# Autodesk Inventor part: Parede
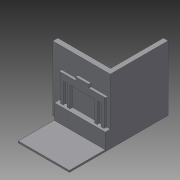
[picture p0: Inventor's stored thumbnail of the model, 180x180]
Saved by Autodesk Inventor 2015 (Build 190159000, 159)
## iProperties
Created: 2015-04
Part Number: Parede
Material: Genérico
Document SubType Name: Modeling
Designer: Felipe
Density: 1 g/cm^3
Appearance: Padrão
Author: Felipe
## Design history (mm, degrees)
sketch "Sketch1"
  geometry: L1 (0, 0)-(16900, 0); L2 (16900, 0)-(16900, 17000); L3 (16900, 17000)-(15500, 17000); L4 (15500, 17000)-(15500, 1500); L5 (15500, 1500)-(0, 1500); L6 (0, 1500)-(0, 0)
  constraints: 12 end point, 5 perpendicular, 1 horizontal
  dimensions: "d0" = 1500 distance between parallel lines of L5 L1; "d1" = 1400 distance between parallel lines of L2 L4; "d2" = 16900 distance between parallel lines of L2 L6; "d3" = 17000 distance between parallel lines of L3 L1
extrude "Extrusion1" new body sketch "Sketch1" distance "d4" = 19000; taper "d5" = 0 deg
sketch "Sketch2"
  geometry: L1 (16900, 0)-(1880, 0); L2 (1880, 0)-(1880, 500); L3 (1880, 500)-(16900, 500); L4 (16900, 500)-(16900, 0); L5 (0, 0)-(16900, 0) reference; L6 (16900, 0)-(16900, 19000) reference; L7 (0, 19000)-(16900, 19000) reference; L8 (0, 0)-(0, 19000) reference; L9 (16900, 0)-(16900, 19000) reference; L10 (0, 0)-(16900, 0) reference
  constraints: 8 end point, 2 collinear, 2 parallel, 1 horizontal, 1 perpendicular
  dimensions: "d6" = 15020 distance between parallel lines of L4 L2; "d7" = 500 distance between parallel lines of L3 L1
extrude "Extrusion2" join sketch "Sketch2" distance "d8" = 12010; taper "d9" = 0 deg
sketch "Sketch3"
  geometry: L1 (1880, -18500)-(16900, -18500) reference; L2 (16900, -18500)-(16900, 0) reference; L3 (0, 0)-(16900, 0) reference; L4 (0, -19000)-(0, 0) reference; L5 (0, -19000)-(1880, -19000) reference; L6 (1880, -19000)-(1880, -18500) reference; L7 (1880, -19000)-(16900, -19000) reference; L8 (16900, -19000)-(16900, -18500) reference; L9 (16900, -18500)-(1880, -18500) reference; L10 (1880, -18500)-(1880, -19000) reference; L11 (16900, -14000)-(1980, -14000); L12 (1980, -14000)-(1980, -19000); L13 (16900, -18500)-(1880, -18500); L14 (16900, -14000)-(16900, -18500); L15 (1980, -14000)-(16900, -14000); L16 (16900, -14000)-(16900, -18500); L17 (16900, -18500)-(1980, -18500); L18 (1980, -18500)-(1980, -14000); 1 further point
  constraints: 16 end point, 3 equal length, 3 perpendicular, 2 point on line, 1 horizontal, 1 vertical
  dimensions: "d11" = 4500 distance between parallel lines of L11 L1
extrude "Extrusion4" join sketch "Sketch3" distance "d14" = 1480; taper "d15" = 0 deg
sketch "Sketch4"
  geometry: L1 (1980, -18500)-(1980, -14000) reference; L2 (1980, -14000)-(16900, -14000) reference; L3 (16900, -14000)-(16900, 0) reference; L4 (0, 0)-(16900, 0) reference; L5 (0, -19000)-(0, 0) reference; L6 (0, -19000)-(1880, -19000) reference; L7 (1880, -19000)-(1880, -18500) reference; L8 (1880, -18500)-(1980, -18500) reference; L9 (1980, -14000)-(1980, -18500) reference; L10 (16900, -18500)-(1980, -18500) reference; L11 (16900, -18500)-(16900, -14000) reference; L12 (16900, -18500)-(1880, -18500) reference; L13 (1980, -14000)-(1980, -18500) reference; L14 (2980, -14000)-(2980, -7920); L15 (2980, -7920)-(3800, -7920); L16 (3800, -7920)-(3800, -14000); L17 (4980, -14000)-(4980, -7920); L18 (4980, -7920)-(5800, -7920); L19 (5800, -7920)-(5800, -14000); L20 (12980, -14000)-(12980, -7920); L21 (12980, -7920)-(13800, -7920); L22 (13800, -7920)-(13706.466, -7920); L23 (13800, -7920)-(13800, -14000); L24 (14980, -14000)-(14980, -7920); L25 (14980, -7920)-(15800, -7920); L26 (15500, -19000)-(15500, 0) reference; L27 (15800, -7920)-(15800, -14000); L28 (2980, -7920)-(15800, -7920); L29 (15800, -7920)-(15800, -6420); L30 (15800, -6420)-(2980, -6420); L31 (2980, -6420)-(2980, -7920); L32 (2574, -6000)-(16206, -6000); L33 (2980, -6420)-(2574, -6000); L34 (15800, -6420)-(16206, -6000); L35 (7480, -5000)-(11300, -5000); L36 (7480, -5000)-(7480, -6000); L37 (11300, -5000)-(11300, -6000); 4 further points
  constraints: 46 end point, 8 perpendicular, 5 vertical, 3 horizontal, 3 midpoint, 3 parallel, 3 point on line, 2 vertical alignment, 1 collinear, 9 other
  dimensions: "d16" = 1000 distance between parallel lines of L14 L9; "d17" = 820 distance between parallel lines of L16 L14; "d18" = 6080 distance between parallel lines of L2 L15; "d19" = 820 distance of L17.end L18.end; "d20" = 1180 distance between parallel lines of L17 L16; "d21" = 6080 distance between parallel lines of L2 L18; "d22" = 820 distance of L20.end L21.end; "d23" = 7180 distance between parallel lines of L20 L19; "d24" = 6080 distance between parallel lines of L2 L21; "d25" = 820 distance of L24.end L25.end; "d26" = 1180 distance between parallel lines of L24 L23; "d27" = 1500 distance between parallel lines of L30 L28; "d28" = 12820 distance between parallel lines of L29 L31; "d29" = 13632 distance of L32.start L32.end; "d30" = 420 distance between parallel lines of L32 L30; "d31" = 3820 distance of L35.start L35.end; "d32" = 1000 distance between parallel lines of L32 L35
extrude "Extrusion5" join sketch "Sketch4" distance "d33" = 740; taper "d34" = 0 deg
body "Solid1"
node "Projected Loop1"
node "Projected Loop2"
node "Projected Loop3"
node "Projected Loop4"
node "Projected Loop5"
